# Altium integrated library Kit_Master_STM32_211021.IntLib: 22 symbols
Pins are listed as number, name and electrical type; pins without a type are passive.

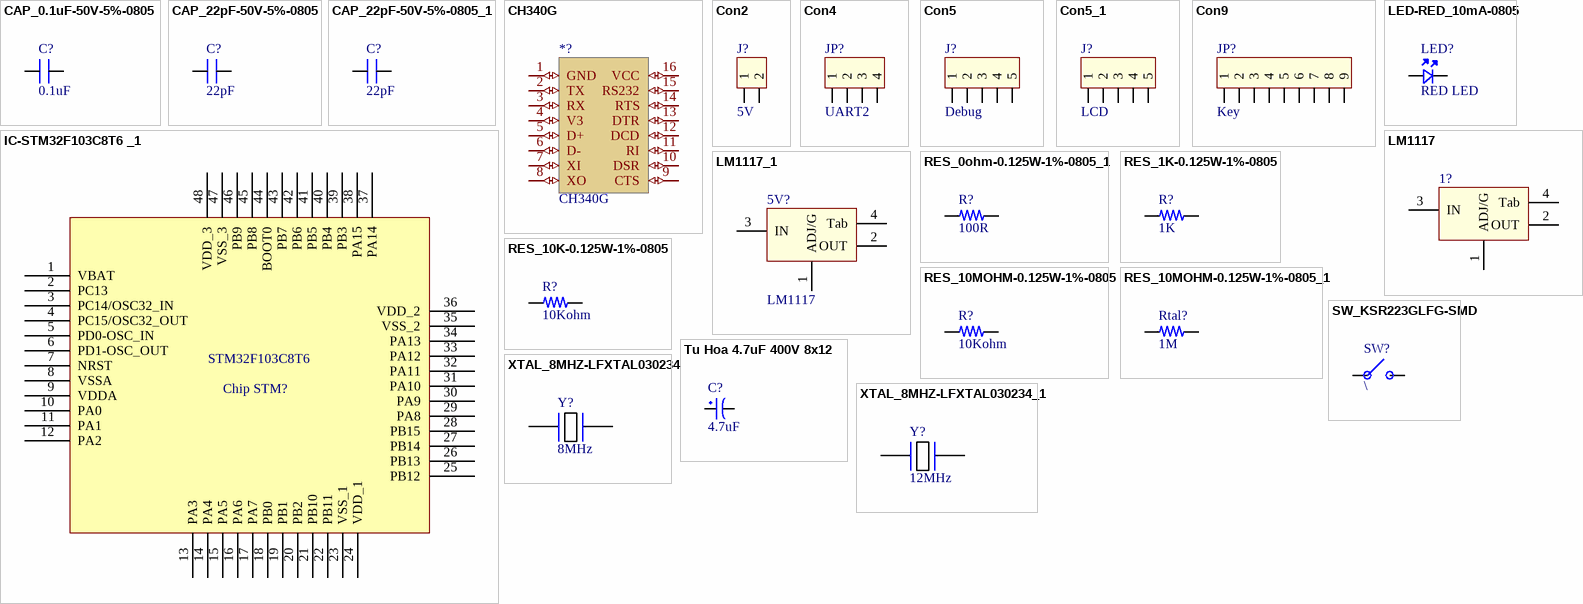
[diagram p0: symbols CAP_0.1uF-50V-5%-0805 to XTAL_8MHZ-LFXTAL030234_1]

## CAP_0.1uF-50V-5%-0805
designator C?, comment 0.1uF
0.1µF ±5% 50V Ceramic Capacitor X7R 0805 (2012 Metric); Manufacturer: KEMET; Manufacturing Part Number: C0805C104J5RACTU
footprint CAP_0805 (Ceramic Capacitor)
pins: 1, 2

## CAP_22pF-50V-5%-0805
designator C?, comment 22pF
22pF ±5% 50V Ceramic Capacitor C0G, NP0 0805 (2012 Metric); Manufacturer: KEMET; Manufacturer Part Number: C0805C220J5GACTU
footprint CAP_0805 (Ceramic Capacitor)
pins: 1, 2

## CAP_22pF-50V-5%-0805_1
designator C?, comment 22pF
22pF ±5% 50V Ceramic Capacitor C0G, NP0 0805 (2012 Metric); Manufacturer: KEMET; Manufacturer Part Number: C0805C220J5GACTU
footprint CAP_0805 (Ceramic Capacitor)
pins: 1, 2

## CH340G
designator *?
footprint CH340G
pins: 1 GND (io), 2 TX (io), 3 RX (io), 4 V3 (io), 5 D+ (io), 6 D- (io), 7 XI (io), 8 XO (io), 9 CTS (io), 10 DSR (io), 11 RI (io), 12 DCD (io), 13 DTR (io), 14 RTS (io), 15 RS232 (io), 16 VCC (io)

## Con2
designator J?, comment 5V
Connector 2
footprint CON2
pins: 1, 2

## Con4
designator JP?, comment UART2
Connector 4
footprint CON4
pins: 1, 2, 3, 4

## Con5
designator J?, comment Debug
Connector 5
footprint CON5
pins: 1, 2, 3, 4, 5

## Con5_1
designator J?, comment LCD
Connector 5
footprint CON5
pins: 1, 2, 3, 4, 5

## Con9
designator JP?, comment Key
Connector 9
footprint CON9
pins: 1, 2, 3, 4, 5, 6, 7, 8, 9

## IC-STM32F103C8T6 _1
designator Chip STM?, comment STM32F103C8T6
ARM® Cortex®-M3 STM32F1 Microcontroller IC 32-Bit 72MHz 64KB (64K x 8) FLASH; Manufacturer: STMicroelectronics
footprint LQFP-48_19.6_393_58X11_SMD (48LQFP)
pins: 1 VBAT, 2 PC13, 3 PC14/OSC32_IN, 4 PC15/OSC32_OUT, 5 PD0-OSC_IN, 6 PD1-OSC_OUT, 7 NRST, 8 VSSA, 9 VDDA, 10 PA0, 11 PA1, 12 PA2, 13 PA3, 14 PA4, 15 PA5, 16 PA6, 17 PA7, 18 PB0, 19 PB1, 20 PB2, 21 PB10, 22 PB11, 23 VSS_1, 24 VDD_1, 25 PB12, 26 PB13, 27 PB14, 28 PB15, 29 PA8, 30 PA9, 31 PA10, 32 PA11, 33 PA12, 34 PA13, 35 VSS_2, 36 VDD_2, 37 PA14, 38 PA15, 39 PB3, 40 PB4, 41 PB5, 42 PB6, 43 PB7, 44 BOOT0, 45 PB8, 46 PB9, 47 VSS_3, 48 VDD_3

## LED-RED_10mA-0805
designator LED?, comment RED LED
Red 621nm LED Indication - Discrete 2V 0805 (2012 Metric); Manufacturer: Lite-On Inc.; Manufacturer Part Number: LTST-C170EKT
footprint LED_0805 (LED)
pins: A, K

## LM1117
designator 1?
3v3; Value: LM317
footprint SOT223-4N (SOT223, 4-Leads, Body 6.5x3.5mm, Pitch 2.3mm, Lead Span 7mm, IPC Medium Density)
pins: 1 ADJ/G, 2 OUT, 3 IN, 4 Tab

## LM1117_1
designator 5V?, comment LM1117
3v3; Value: LM317
footprint SOT223-4N (SOT223, 4-Leads, Body 6.5x3.5mm, Pitch 2.3mm, Lead Span 7mm, IPC Medium Density)
pins: 1 ADJ/G, 2 OUT, 3 IN, 4 Tab

## RES_0ohm-0.125W-1%-0805_1
designator R?, comment 100R
1000Ohms ±1% 0.125W, 1/8W Chip Resistor 0805 (2012 Metric) Moisture Resistant Thick Film; Manufacturer: 垈㎵á; Manufacturer Part Number: RC0805FR-071KL
footprint RES_0805 (Resister)
pins: 1, 2

## RES_1K-0.125W-1%-0805
designator R?, comment 1K
1 kOhms ±1% 0.125W, 1/8W Chip Resistor 0805 (2012 Metric) Moisture Resistant Thick Film; Manufacturer: 垈㎵á; Manufacturer Part Number: RC0805FR-071KL
footprint RES_0805 (Resister)
pins: 1, 2

## RES_10K-0.125W-1%-0805
designator R?, comment 10Kohm
10 kOhms ±1% 0.125W, 1/8W Chip Resistor 0805 (2012 Metric) Moisture Resistant Thick Film; Manufacturer: Yageo; Manufacturing Part Number: RC0805FR-0710KL
footprint RES_0805 (Resister)
pins: 1, 2

## RES_10MOHM-0.125W-1%-0805
designator R?, comment 10Kohm
10 MOhms ±1% 0.125W, 1/8W Chip Resistor 0805 (2012 Metric) Automotive AEC-Q200, High Voltage Thick Film; Manufacturer: Rohm Semiconductor; Manufacturing Part Number: KTR10EZPF1005
footprint RES_0805 (Resister)
pins: 1, 2

## RES_10MOHM-0.125W-1%-0805_1
designator Rtal?, comment 1M
10 MOhms ±1% 0.125W, 1/8W Chip Resistor 0805 (2012 Metric) Automotive AEC-Q200, High Voltage Thick Film; Manufacturer: Rohm Semiconductor; Manufacturing Part Number: KTR10EZPF1005
footprint RES_0805 (Resister)
pins: 1, 2

## SW_KSR223GLFG-SMD
designator SW?, comment \
Tactile Switch SPST-NO Top Actuated Surface Mount; Manufacturer: C&K; Manufacturing Part Number: KSR223GLFG
footprint SW_342_SMD (CASE: SMD)
pins: 1, 2

## Tu Hoa 4.7uF 400V 8x12
designator C?, comment 4.7uF
Cắm; Don_Vi: Con; So_Chan: 2; Ten_Linh_Kien: Tụ Hóa 4.7uF 400V 8x12MM; Ma_Hang: MH003744
footprint tu hoa 8mm
pins: 1, 2

## XTAL_8MHZ-LFXTAL030234
designator Y?, comment 8MHz
Crystals 8MHz 22pF -20C 70C; Manufacturer: IQD Frequency Products; Manufacturing Part Number: LFXTAL030234Reel
footprint XTAL_314_240X47_SMD (CASE: TH)
pins: 1, 2

## XTAL_8MHZ-LFXTAL030234_1
designator Y?, comment 12MHz
Crystals 8MHz 22pF -20C 70C; Manufacturer: IQD Frequency Products; Manufacturing Part Number: LFXTAL030234Reel
footprint XTAL_314_240X47_SMD (CASE: TH)
pins: 1, 2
